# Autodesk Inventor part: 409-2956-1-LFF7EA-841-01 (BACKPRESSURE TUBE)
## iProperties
Created: 2010-09
Part Number: 409-2956-1-LFF7EA-841-01 (BACKPRESSURE TUBE)
Material: 1/2"OD TUBE - SS
Document SubType Name: Modeling
Designer: S. Boerckel
Engineer: Steve Boerckel
Mass: 246.239 g
Surface Area: 534.079 cm^2
Volume: 30.4752 cm^3
Density: 8.08 g/cm^3
Description: BACK PRESSURE TUBE
Length: 28.912 in
Author: S. Boerckel
Revision Number: 0
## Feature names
1. Sweep1
